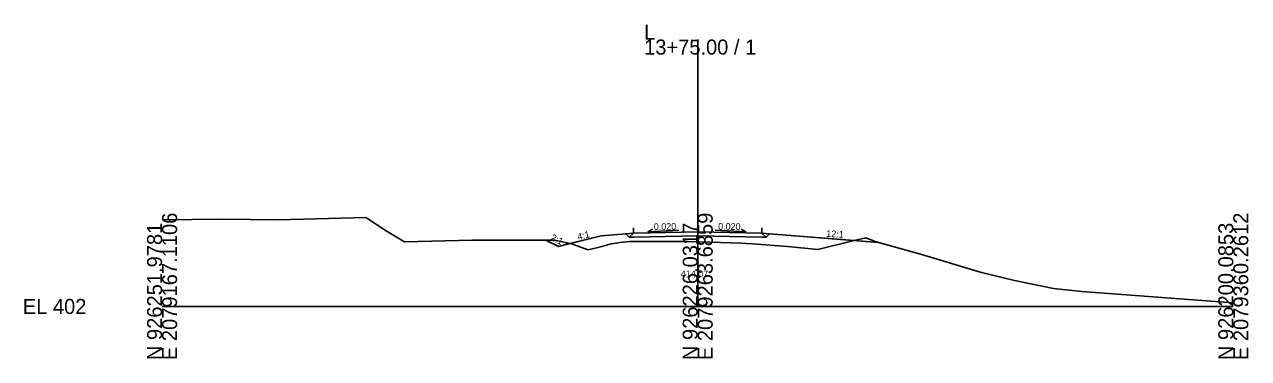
# Model space of a CAD drawing. Extents: x -26 to 10503, y -10 to 9546.
# Drawn here: x -25.7 to 202.8, y 7490.3 to 7552.5 of the extents above; entities that cross this region are included whole.
import ezdxf

# ---------------------------------------------------------------- set-up
doc = ezdxf.new("R2010")
doc.units = 0
for name, color, linetype in [('Default', 7, 'Continuous'), ('Exist XS Center Line Elevation Label', 7, 'Continuous'), ('Exist XS Ground Line', 7, 'Continuous'), ('Old_Level_63', 7, 'Continuous'), ('Prop XS Ditch Slope Text', 7, 'Continuous'), ('Prop XS Dump Level', 7, 'Continuous'), ('Prop XS EOT Tick Mark', 7, 'Continuous'), ('Prop XS Finish Grade', 7, 'Continuous'), ('Prop XS Finish Grade Earthwork', 7, 'Continuous'), ('Prop XS Finish Grade Pavement', 7, 'Continuous'), ('Prop XS Pvmt Edge Slope', 7, 'Continuous'), ('Prop XS SE Text', 7, 'Continuous'), ('Prop XS Side Slope Text', 7, 'Continuous'), ('Prop XS Subgrade Earthwork', 7, 'Continuous')]:
    doc.layers.add(name, color=color, linetype=linetype)

msp = doc.modelspace()

# ---------------------------------------------------------------- linework, layer by layer
at = {"layer": 'Default'}
for points in [[(73.99, 7511.18), (71.63, 7512.36), (73.3, 7512.36), (76.15, 7511.72)], [(88, 7512.91), (87.23, 7512.9), (86.58, 7513.55), (81.99, 7513.18), (76.15, 7511.72), (76.65, 7511.6), (79.54, 7510.57), (82.09, 7511.19), (83.87, 7511.7), (85.54, 7511.92), (87.25, 7512.11), (91.57, 7512.13), (98.2, 7512.13), (100, 7512.07), (102.24, 7512), (108.18, 7511.79), (109.04, 7511.75), (110.25, 7511.69), (116.79, 7511.19), (122.45, 7510.61), (129.24, 7512.27), (129.28, 7512.28), (113.42, 7513.55), (112.77, 7512.9), (112, 7512.91), (100, 7513.15)], [(129.28, 7512.28), (131.39, 7512.81), (133.32, 7512.04), (133.72, 7511.92)]]:
    msp.add_lwpolyline(points, close=True, dxfattribs=at)
at = {"layer": 'Exist XS Ground Line'}
for p, q in [((21.72, 7516.12), (38.04, 7516.58)), ((38.04, 7516.58), (41.86, 7514.07)), ((0, 7516.12), (11.19, 7516.28)), ((11.19, 7516.28), (21.72, 7516.12)), ((41.86, 7514.07), (45.28, 7512.03)), ((45.28, 7512.03), (57.86, 7512.34)), ((57.86, 7512.34), (73.3, 7512.36)), ((73.3, 7512.36), (76.65, 7511.6)), ((83.87, 7511.7), (85.54, 7511.92)), ((85.54, 7511.92), (87.25, 7512.11)), ((87.25, 7512.11), (91.57, 7512.13)), ((91.57, 7512.13), (98.2, 7512.13)), ((98.2, 7512.13), (100, 7512.07)), ((100, 7512.07), (102.24, 7512)), ((102.24, 7512), (108.18, 7511.79)), ((122.45, 7510.61), (129.24, 7512.27)), ((129.24, 7512.27), (131.39, 7512.81)), ((131.39, 7512.81), (133.32, 7512.04)), ((133.32, 7512.04), (141.57, 7509.74)), ((76.65, 7511.6), (79.54, 7510.57)), ((79.54, 7510.57), (82.09, 7511.19)), ((82.09, 7511.19), (83.87, 7511.7)), ((108.18, 7511.79), (109.04, 7511.75)), ((109.04, 7511.75), (110.25, 7511.69)), ((110.25, 7511.69), (116.79, 7511.19)), ((116.79, 7511.19), (122.45, 7510.61)), ((141.57, 7509.74), (152.96, 7506.31)), ((152.96, 7506.31), (159.17, 7504.85)), ((159.17, 7504.85), (166.4, 7503.37)), ((166.4, 7503.37), (171.71, 7502.8)), ((171.71, 7502.8), (200, 7500.7))]:
    msp.add_line(p, q, dxfattribs=at)
at = {"layer": 'Old_Level_63'}
for p, q in [((100, 7500), (100, 7549.75)), ((0, 7500), (100, 7500)), ((100, 7500), (200, 7500))]:
    msp.add_line(p, q, dxfattribs=at)
at = {"layer": 'Prop XS EOT Tick Mark'}
for p, q in [((88, 7513.66), (88, 7514.66)), ((112, 7513.66), (112, 7514.66))]:
    msp.add_line(p, q, dxfattribs=at)
at = {"layer": 'Prop XS Finish Grade'}
for p, q in [((88, 7513.66), (86.58, 7513.55)), ((112, 7513.66), (113.42, 7513.55))]:
    msp.add_line(p, q, dxfattribs=at)
at = {"layer": 'Prop XS Finish Grade Earthwork'}
for p, q in [((73.99, 7511.18), (71.63, 7512.36)), ((81.99, 7513.18), (73.99, 7511.18)), ((86.58, 7513.55), (81.99, 7513.18)), ((113.42, 7513.55), (133.72, 7511.92))]:
    msp.add_line(p, q, dxfattribs=at)
at = {"layer": 'Prop XS Finish Grade Pavement'}
for p, q in [((88, 7513.66), (100, 7513.9)), ((100, 7513.9), (112, 7513.66))]:
    msp.add_line(p, q, dxfattribs=at)
at = {"layer": 'Prop XS Pvmt Edge Slope'}
for p, q in [((88, 7513.66), (87.23, 7512.9)), ((112, 7513.66), (112.77, 7512.9))]:
    msp.add_line(p, q, dxfattribs=at)
at = {"layer": 'Prop XS SE Text'}
for points in [[(96.49, 7514.21), (90.73, 7513.93), (91.58, 7514.39)], [(103.23, 7514.21), (108.98, 7513.94), (108.13, 7514.4)]]:
    msp.add_lwpolyline(points, dxfattribs=at)
at = {"layer": 'Prop XS Subgrade Earthwork'}
for p, q in [((87.23, 7512.9), (86.58, 7513.55)), ((88, 7512.91), (87.23, 7512.9)), ((100, 7513.15), (88, 7512.91)), ((112, 7512.91), (100, 7513.15)), ((112, 7512.91), (112.77, 7512.9)), ((112.77, 7512.9), (113.42, 7513.55))]:
    msp.add_line(p, q, dxfattribs=at)

# ---------------------------------------------------------------- texts
at = {"layer": 'Exist XS Center Line Elevation Label'}
msp.add_text('414.07', height=1.25, rotation=360, dxfattribs=at).set_placement((96.84, 7505.45))
at = {"layer": 'Old_Level_63'}
for s, p in [('L', (90, 7549.75)), ('13+75.00 / 1', (90, 7546.95)), ('EL 402', (-26, 7498.6))]:
    msp.add_text(s, height=2.8, dxfattribs=at).set_placement(p)
for s, p in [('E 2079167.1106', (2.8, 7490)), ('E 2079263.6859', (102.8, 7490)), ('E 2079360.2612', (202.8, 7490)), ('N 926251.9781', (0, 7490)), ('N 926226.0317', (100, 7490)), ('N 926200.0853', (200, 7490))]:
    msp.add_text(s, height=2.8, rotation=90, dxfattribs=at).set_placement(p)
at = {"layer": 'Prop XS Ditch Slope Text'}
for s, rotation, p in [('12:1', 356.5563, (123.97, 7512.99)), ('4:1', 14.0362, (77.7, 7512.35))]:
    msp.add_text(s, height=1.25, rotation=rotation, dxfattribs=at).set_placement(p)
at = {"layer": 'Prop XS Dump Level'}
for p in [(80, 7512.98), (120, 7512.98)]:
    msp.add_text('Case1', height=0.04, dxfattribs=at).set_placement(p)
at = {"layer": 'Prop XS SE Text'}
for rotation, p in [(1.1458, (91.81, 7514.24)), (358.8542, (103.81, 7514.33))]:
    msp.add_text('0.020', height=1.25, rotation=rotation, dxfattribs=at).set_placement(p)
at = {"layer": 'Prop XS Side Slope Text'}
msp.add_text('2:1', height=1.25, rotation=333.4349, dxfattribs=at).set_placement((72.42, 7512.45))

doc.saveas('drawing.dxf')
